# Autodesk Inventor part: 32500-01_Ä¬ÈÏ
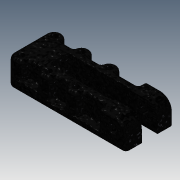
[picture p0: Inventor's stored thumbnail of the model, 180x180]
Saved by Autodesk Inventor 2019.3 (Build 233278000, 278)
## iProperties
Created: 2010-06
Part Number: 32500-01_Ä¬ÈÏ
Material: Ogólny
Document SubType Name: Modeling
Designer: CADENGINEERING4
Density: 1 g/cm^3
Appearance: Czarny
Author: CADENGINEERING4
Revision Number: ÈÎºÎ
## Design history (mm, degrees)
feature "NONE"
node "Bryła1"
